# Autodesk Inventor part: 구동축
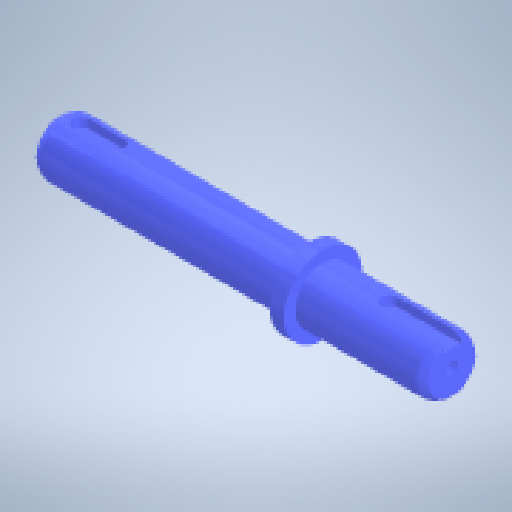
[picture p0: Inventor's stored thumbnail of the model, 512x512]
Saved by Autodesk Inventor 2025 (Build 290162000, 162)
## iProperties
Created: 2026-01
Part Number: 구동축
Material: 강철, 탄소
Document SubType Name: Modeling
Designer: KDI
Density: 7.85 g/cm^3
Appearance: 기본값
Author: jhkim
Sending System: Autodesk Inventor 2026
Preprocessor: ST-DEVELOPER v20.1
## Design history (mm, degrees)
feature "솔리드1"
node "솔리드2"
